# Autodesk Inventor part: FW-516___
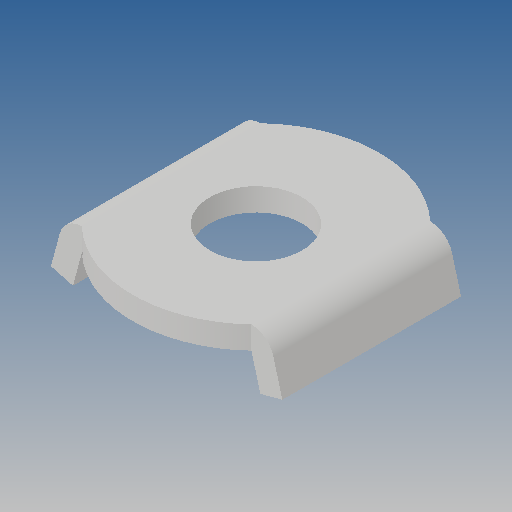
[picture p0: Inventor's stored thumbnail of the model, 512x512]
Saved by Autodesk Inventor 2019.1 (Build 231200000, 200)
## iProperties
Created: 2013-01
Part Number: FW-516___
Material: Ogólny
Document SubType Name: Modeling
Designer: CADENGINEERING4
Density: 1 g/cm^3
Appearance: Domyślna
Author: CADENGINEERING4
Revision Number: ÈÎºÎ
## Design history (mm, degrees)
feature "NONE"
node "Bryła1"
